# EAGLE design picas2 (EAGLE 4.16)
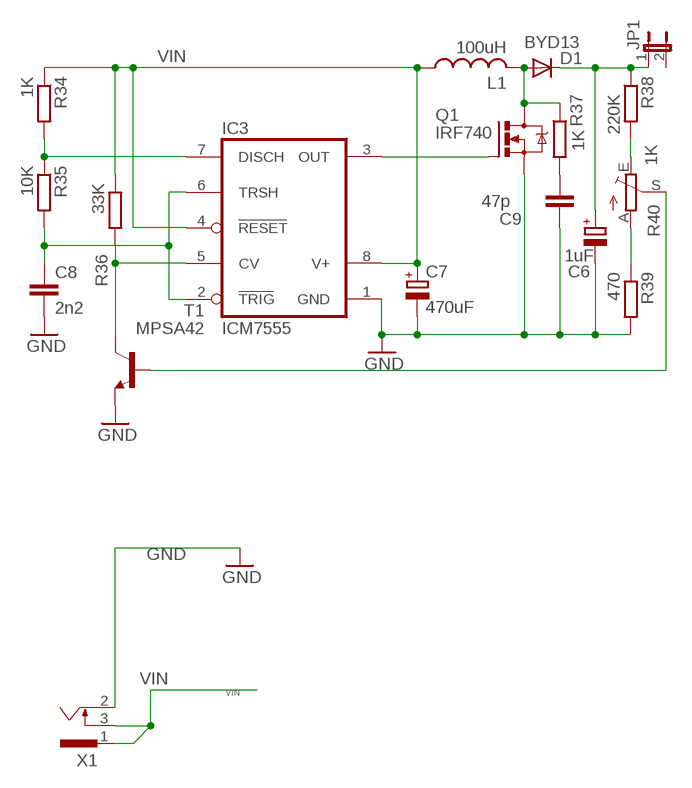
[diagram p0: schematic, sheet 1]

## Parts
C6  1uF  CPOL-EUE5-4  [E5-4]
C7  470uF  CPOL-EUE3.5-8  [E3,5-8]
C8  2n2  C-EU050-024X044  [C050-024X044]
C9  47p  C-EU025-025X050  [C025-025X050]
D1  BYD13  [SOD81]
IC3  ICM7555  [DIL08]
JP1  JP1E  [JP1]
L1  100uH  L-USTJ3-U1  [TJ3-U1]
Q1  IRF740  [TO220BV]
R34  1K  R-EU_0207/10  [0207/10]
R35  10K  R-EU_0207/10  [0207/10]
R36  33K  R-EU_0207/10  [0207/10]
R37  1K  R-EU_0207/10  [0207/10]
R38  220K  R-EU_0204/2V  [0204V]
R39  470  R-EU_0204/7  [0204/7]
R40  1K  TRIM_EU-CA6V  [CA6V]
T1  MPSA42  -NPN-TO92  [TO92]
X1  733989-55  [733989-5]

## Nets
+190BV [power]: C6.+ D1.C JP1.1 R38.1
GND [power]: C6.- C7.- C8.2 C9.2 IC3.1(GND) Q1.S R39.2 T1.1(E) X1.2
N$3: IC3.5(CV) R36.2 T1.3(C)
N$8: IC3.7(DISCH) R34.2 R35.1
N$45: C8.1 IC3.2(TRIG) IC3.6(TRSH) R35.2
N$47: IC3.3(OUT) Q1.G
N$49: C9.1 R37.2
N$51 [power]: D1.A L1.2 Q1.D R37.1
N$54: R39.1 R40.A
N$55: R38.2 R40.E
N$56: R40.S T1.2(B)
VIN [power]: C7.+ IC3.4(RESET) IC3.8(V+) L1.1 R34.1 R36.1 X1.1 X1.3
Unconnected: JP1.2

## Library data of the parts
C6 C7 = rcl:CPOL-EU: POLARIZED CAPACITOR, European symbol
C8 C9 = rcl:C-EU: CAPACITOR, European symbol
D1 = diode:BYD13: DIODE
IC3 = maxim:ICM7555: TIMER
JP1 = jumper:JP1E: JUMPER
L1 = rcl:L-US: INDUCTOR, American symbol
Q1 = transistor-power:IRF740: N-CHANNEL MOS FET
R34-R39 = rcl:R-EU_: RESISTOR, European symbol
R40 = pot:TRIM_EU-: POTENTIOMETER
T1 = transistor:*-NPN-: NPN Transistror
X1 = con-conrad:733989-55: FEMALE PRINT CONNECTOR Außen-Ø 4,2 mm, Innen 1.1 mm FUK HING Industries, distributor Conrad

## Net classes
1 power: width 1.016 mm

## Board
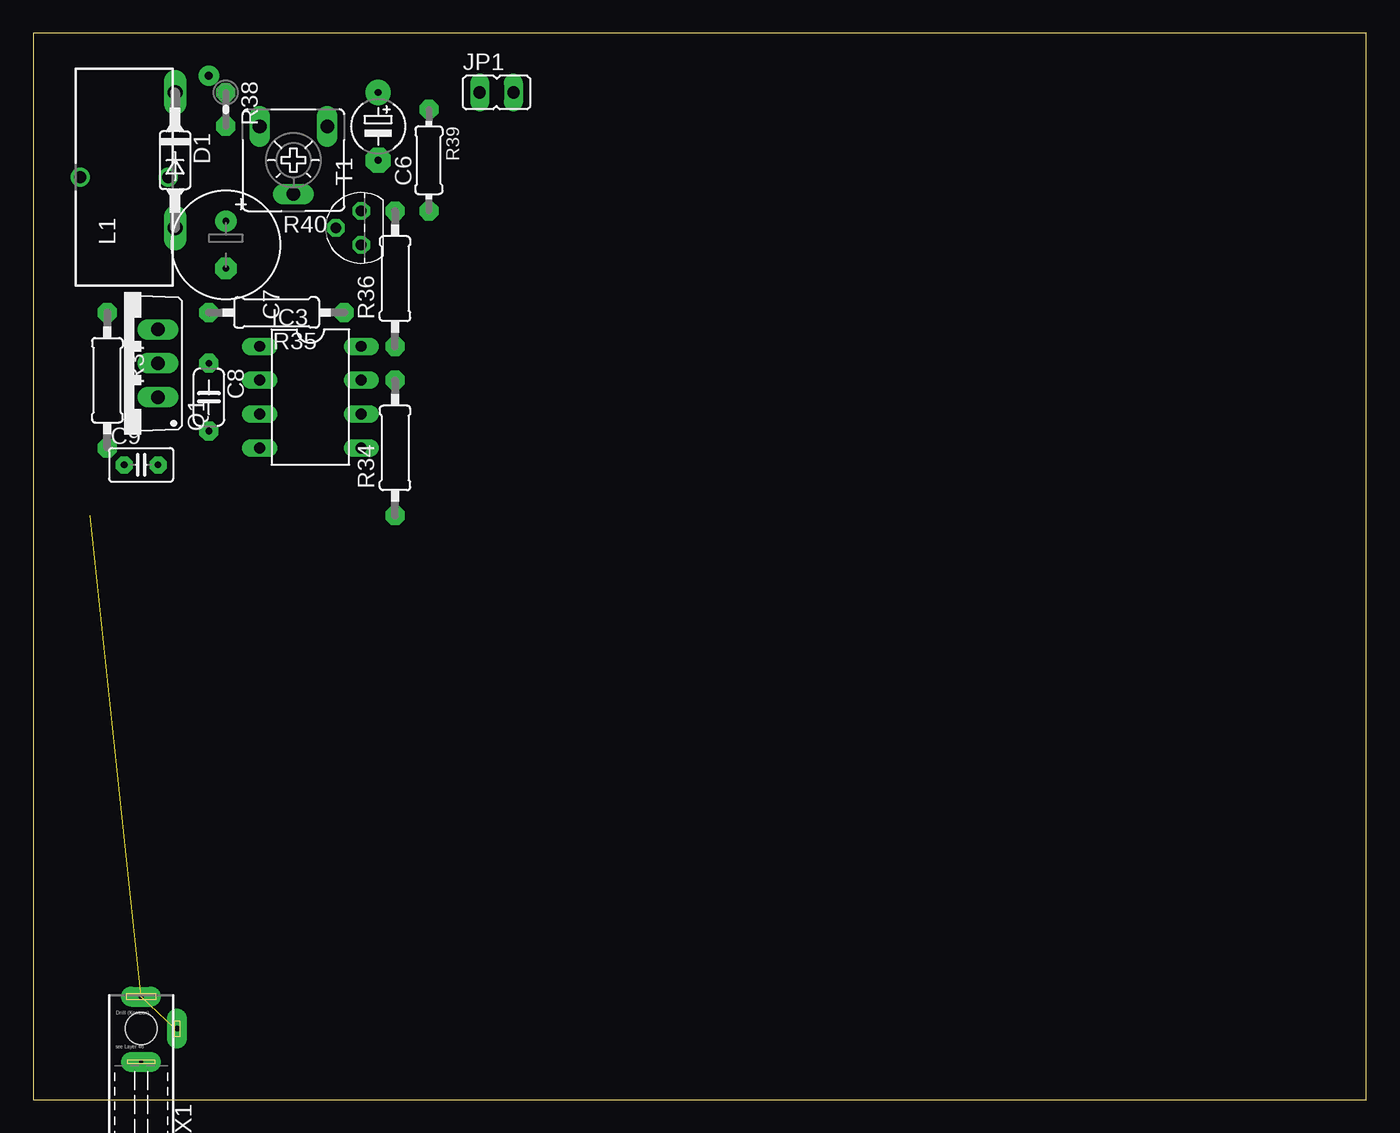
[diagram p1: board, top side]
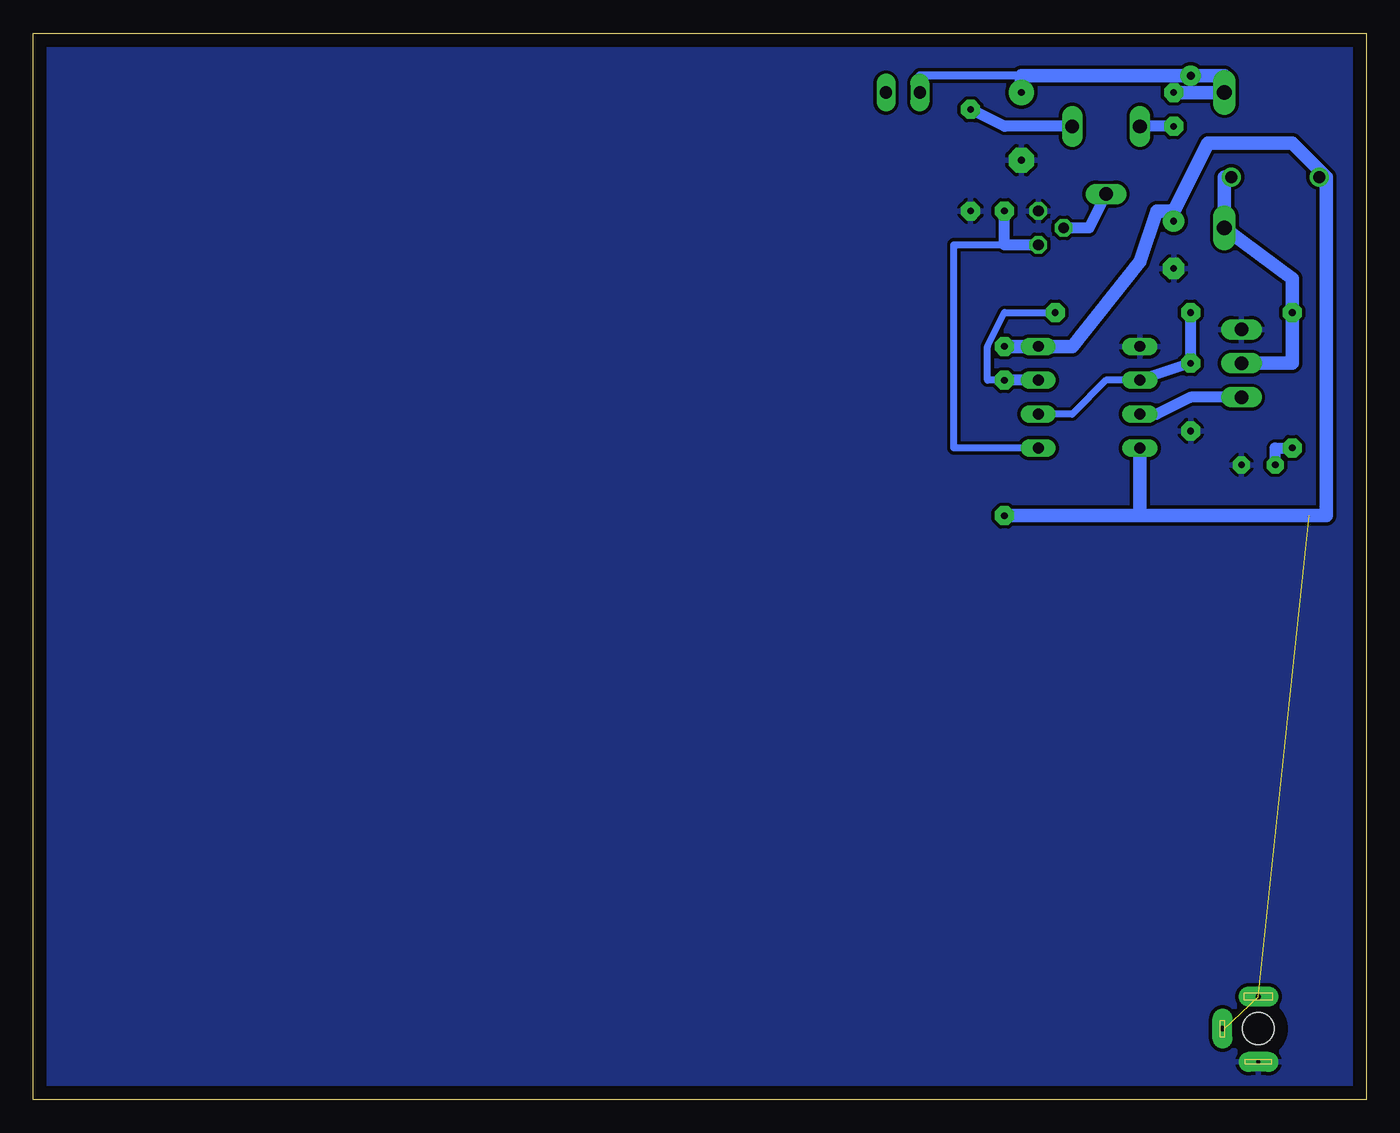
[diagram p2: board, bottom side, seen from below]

Size 100 x 80 mm. Coordinates in mm from the lower left corner, seen from the top.
Outline: 0,0 100,0 100,80 0,80 0,0
Copper layers (1*16): Top 0.035mm / dielectric 1.5mm / Bottom 0.035mm
Design rules "default": minimum track width 20mil, minimum drill 24mil, track to track 10mil, track to pad 10mil, pad to pad 8mil, via to via 8mil, smd to smd 8mil, copper to edge 40mil, drill to drill 8mil, minimum pad ring 10mil, minimum via ring 18mil, stop-mask expansion 4mil, vias tented up to drill 0mil, thermal gap 10mil

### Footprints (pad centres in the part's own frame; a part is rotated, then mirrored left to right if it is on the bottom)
E5-4 = drill 0.5 pad 1.905 round: + -2.54,0 | drill 0.5 pad 1.905 octagon: - 2.54,0
E3,5-8 = drill 0.5 pad 1.6 round: + -1.778,0 | drill 0.5 pad 1.6 octagon: - 1.778,0
C050-024X044 = drill 0.5 pad 1.422 octagon: 1 -2.54,0; 2 2.54,0
C025-025X050 = drill 0.5 pad 1.27 octagon: 1 -1.27,0; 2 1.27,0
SOD81 = drill 1.118 long: A 5.08,0; C -5.08,0
DIL08 = drill 0.813 long: 1 -3.81,-3.81; 2 -1.27,-3.81; 3 1.27,-3.81; 4 3.81,-3.81; 5 3.81,3.81; 6 1.27,3.81; 7 -1.27,3.81; 8 -3.81,3.81
JP1 = drill 0.914 long: 1 0,-1.27; 2 0,1.27
TJ3-U1 = drill 0.9 round: 1 -3.3,0; 2 3.3,0
TO220BV = drill 1.016 long: D 0,-2.54; G -2.54,-2.54; S 2.54,-2.54
0207/10 = drill 0.5 pad 1.422 octagon: 1 -5.08,0; 2 5.08,0
0204V = drill 0.5 pad 1.422 octagon: 1 -1.27,0; 2 1.27,0
0204/7 = drill 0.5 pad 1.422 octagon: 1 -3.81,0; 2 3.81,0
CA6V = drill 1.016 long: A -2.54,-2.54; E 2.54,-2.54; S 0,2.54
TO92 = drill 0.813 octagon: 1 1.27,0; 2 0,1.905; 3 -1.27,0
733989-5 = drill 0.4 pad 1.5 long: 1 0,5.82; 3 2.7,3.42 | drill 0.3 pad 1.5 long: 2 0,0.92 | hole 2.4: 0,3.42

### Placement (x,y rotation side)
C6  25.87,73.02 270 top
C7  14.44,64.13 270 top
C8  13.17,52.7 270 top
C9  8.09,47.62 0 top
D1  10.63,70.48 270 top
IC3  20.79,52.7 270 top
JP1  34.76,75.56 270 top
L1  6.82,69.21 0 top
Q1  6.82,55.24 90 top
R34  27.14,48.89 90 top
R35  18.25,59.05 180 top
R36  27.14,61.59 90 top
R37  5.55,53.97 270 top
R38  14.44,74.29 270 top
R39  29.68,70.48 270 top
R40  19.52,70.48 180 top
T1  24.6,65.4 90 top
X1  8.09,1.9 0 top

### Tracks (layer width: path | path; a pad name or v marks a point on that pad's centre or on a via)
+190BV  (via drill 0.6)
  Bottom 0.61: JP1.1 33.49,76.83 25.87,76.83
  Bottom 1.016: R38.1 D1.C 10.63,76.83 v13.17,76.83 25.87,76.83 C6.+
GND
  pour Bottom: -3.34,81.91 -3.34,-3.18 105.88,-3.18 104.61,-3.18 104.61,81.91
N$3
  Bottom 0.508: 27.14,64.13 30.95,64.13 30.95,48.89 IC3.5
  Bottom 0.813: T1.3 27.14,64.13 R36.2
N$8
  Bottom 0.508: R35.1 27.14,59.05 28.41,56.51 28.41,53.97 R34.2
  Bottom 0.813: IC3.7 R34.2
N$45
  Bottom 0.508: IC3.6 22.06,51.43 19.52,53.97 IC3.2
  Bottom 0.813: IC3.2 C8.1 R35.2
N$47
  Bottom 0.813: IC3.3 15.71,51.43 13.17,52.7 Q1.G
N$49
  Bottom 0.813: C9.1 6.82,48.89 R37.2
N$51
  Bottom 1.016: L1.2 10.63,69.21 D1.A 5.55,61.59 | 5.55,61.59 R37.1 | 5.55,61.59 5.55,55.24 Q1.D
N$54
  Bottom 0.813: R39.1 27.14,73.02 R40.A
N$55
  Bottom 0.813: R38.2 R40.E
N$56
  Bottom 0.813: T1.2 20.79,65.4 R40.S
VIN  (2 unrouted)
  Bottom 0.406: X1.3 10.63,5.32
  Bottom 1.016: R36.1 IC3.8 22.06,56.51 16.98,62.86 15.71,66.67 14.44,66.67 | 14.44,66.67 11.9,71.75 5.55,71.75 3.01,69.21 | 3.01,69.21 L1.1 | 14.44,66.67 C7.+ | 16.98,43.81 IC3.4 | 16.98,43.81 R34.1 | 3.01,69.21 3.01,43.81 4.28,43.81 16.98,43.81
